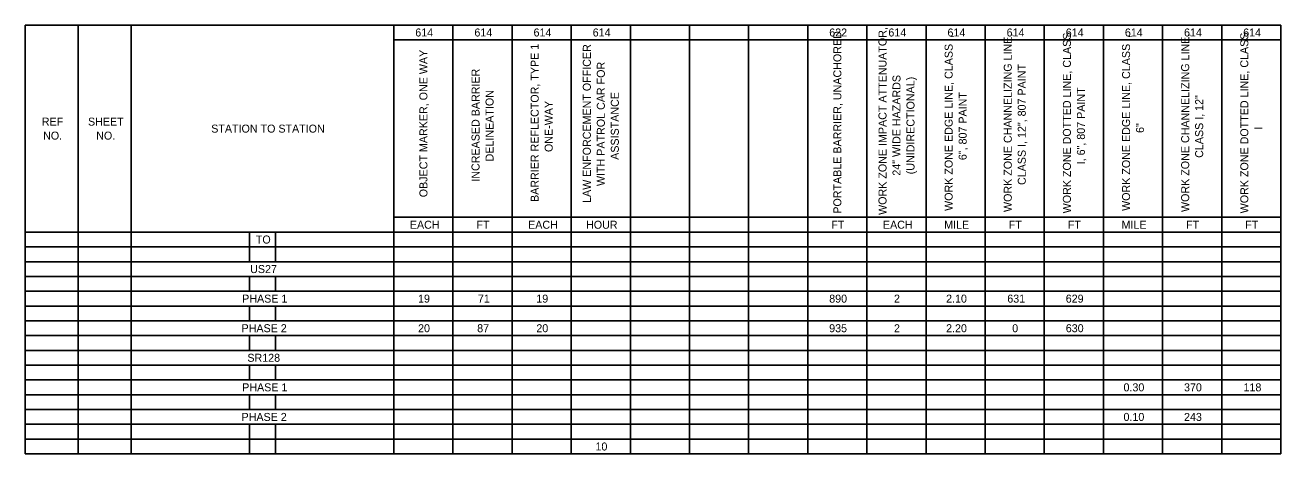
# Model space of a CAD drawing. Extents: x 0 to 86.6, y -18.4 to 22.
# Drawn here: x 52.83 to 86.56, y 9.09 to 20.61 of the extents above; entities that cross this region are included whole.
import ezdxf

# ---------------------------------------------------------------- set-up
doc = ezdxf.new("R2010")
doc.units = 0
doc.layers.add('SH_Text', color=7, linetype='Continuous')

msp = doc.modelspace()

# ---------------------------------------------------------------- linework, layer by layer
at = {"layer": 'SH_Text'}
for p, q in [((52.826, 20.609), (86.562, 20.609)), ((52.826, 20.609), (52.826, 9.091)), ((54.251, 20.609), (54.251, 9.091)), ((55.677, 20.609), (55.677, 9.091)), ((62.732, 20.609), (62.732, 9.091)), ((64.321, 20.609), (64.321, 9.091)), ((65.909, 20.609), (65.909, 9.091)), ((67.498, 20.609), (67.498, 9.091)), ((69.087, 20.609), (69.087, 9.091)), ((70.675, 20.609), (70.675, 9.091)), ((72.264, 20.609), (72.264, 9.091)), ((73.853, 20.609), (73.853, 9.091)), ((75.441, 20.609), (75.441, 9.091)), ((77.03, 20.609), (77.03, 9.091)), ((78.619, 20.609), (78.619, 9.091)), ((80.207, 20.609), (80.207, 9.091)), ((81.796, 20.609), (81.796, 9.091)), ((83.385, 20.609), (83.385, 9.091)), ((84.973, 20.609), (84.973, 9.091)), ((86.562, 20.609), (86.562, 9.091)), ((62.732, 20.212), (86.562, 20.212)), ((62.732, 15.446), (86.562, 15.446)), ((52.826, 15.048), (86.562, 15.048)), ((58.854, 15.048), (58.854, 14.254)), ((59.555, 15.048), (59.555, 14.254)), ((52.826, 14.651), (86.562, 14.651)), ((52.826, 14.254), (86.562, 14.254)), ((52.826, 13.857), (86.562, 13.857)), ((58.854, 13.857), (58.854, 13.46)), ((59.555, 13.857), (59.555, 13.46)), ((52.826, 13.46), (86.562, 13.46)), ((52.826, 13.063), (86.562, 13.063)), ((58.854, 13.063), (58.854, 12.665)), ((59.555, 13.063), (59.555, 12.665)), ((52.826, 12.665), (86.562, 12.665)), ((52.826, 12.268), (86.562, 12.268)), ((58.854, 12.268), (58.854, 11.871)), ((59.555, 12.268), (59.555, 11.871)), ((52.826, 11.871), (86.562, 11.871)), ((52.826, 11.474), (86.562, 11.474)), ((58.854, 11.474), (58.854, 11.077)), ((59.555, 11.474), (59.555, 11.077)), ((52.826, 11.077), (86.562, 11.077)), ((52.826, 10.68), (86.562, 10.68)), ((58.854, 10.68), (58.854, 10.282)), ((59.555, 10.68), (59.555, 10.282)), ((52.826, 10.282), (86.562, 10.282)), ((52.826, 9.885), (86.562, 9.885)), ((58.854, 9.885), (58.854, 9.091)), ((59.555, 9.885), (59.555, 9.091)), ((52.826, 9.488), (86.562, 9.488)), ((52.826, 9.091), (86.562, 9.091))]:
    msp.add_line(p, q, dxfattribs=at)

# ---------------------------------------------------------------- texts
for s, height, p in [('614', 0.2149, (63.308, 20.303)), ('614', 0.2149, (64.896, 20.303)), ('614', 0.2149, (66.485, 20.303)), ('614', 0.2149, (68.074, 20.303)), ('622', 0.2149, (74.429, 20.303)), ('614', 0.2149, (76.017, 20.303)), ('614', 0.2149, (77.605, 20.303)), ('614', 0.2149, (79.194, 20.303)), ('614', 0.2149, (80.783, 20.303)), ('614', 0.2149, (82.371, 20.303)), ('614', 0.2149, (83.96, 20.303)), ('614', 0.2149, (85.549, 20.303)), ('REF', 0.2149, (53.275, 17.909)), ('SHEET', 0.2149, (54.516, 17.909)), ('STATION TO STATION', 0.21494, (57.826, 17.721)), ('NO.', 0.2149, (53.31, 17.533)), ('NO.', 0.2149, (54.736, 17.533)), ('EACH', 0.2149, (63.162, 15.139)), ('FT', 0.2149, (64.953, 15.139)), ('EACH', 0.2149, (66.339, 15.139)), ('HOUR', 0.2149, (67.896, 15.139)), ('FT', 0.2149, (74.485, 15.139)), ('EACH', 0.2149, (75.871, 15.139)), ('MILE', 0.2149, (77.516, 15.139)), ('FT', 0.2149, (79.25, 15.139)), ('FT', 0.2149, (80.839, 15.139)), ('MILE', 0.2149, (82.282, 15.139)), ('FT', 0.2149, (84.016, 15.139)), ('FT', 0.2149, (85.605, 15.139)), ('TO', 0.2149, (59.025, 14.742)), ('US27', 0.2149, (58.872, 13.948)), ('PHASE 1', 0.2149, (58.658, 13.154)), ('19', 0.2149, (63.382, 13.154)), ('71', 0.2149, (64.99, 13.154)), ('19', 0.2149, (66.559, 13.154)), ('890', 0.2149, (74.428, 13.154)), ('2', 0.215, (76.168, 13.154)), ('2.10', 0.2149, (77.568, 13.154)), ('631', 0.2149, (79.212, 13.154)), ('629', 0.2149, (80.782, 13.154)), ('PHASE 2', 0.2149, (58.641, 12.359)), ('20', 0.2149, (63.383, 12.359)), ('87', 0.2149, (64.971, 12.359)), ('20', 0.2149, (66.56, 12.359)), ('935', 0.2149, (74.427, 12.359)), ('2', 0.215, (76.168, 12.359)), ('2.20', 0.2149, (77.568, 12.359)), ('0', 0.215, (79.344, 12.359)), ('630', 0.2149, (80.783, 12.359)), ('SR128', 0.2149, (58.797, 11.565)), ('PHASE 1', 0.2149, (58.658, 10.771)), ('0.30', 0.2149, (82.334, 10.771)), ('370', 0.2149, (83.96, 10.771)), ('118', 0.2149, (85.558, 10.771)), ('PHASE 2', 0.2149, (58.641, 9.976)), ('0.10', 0.2149, (82.334, 9.976)), ('243', 0.2149, (83.96, 9.976)), ('10', 0.2149, (68.149, 9.182))]:
    msp.add_text(s, height=height, dxfattribs=at).set_placement(p)
for s, height, p in [('PORTABLE BARRIER, UNACHORED', 0.21494, (74.754, 15.543)), ('WORK ZONE IMPACT ATTENUATOR, ', 0.21494, (75.967, 15.51)), ('WORK ZONE EDGE LINE, CLASS I, ', 0.21494, (77.744, 15.618)), ('WORK ZONE CHANNELIZING LINE, ', 0.21494, (79.332, 15.588)), ('WORK ZONE DOTTED LINE, CLASS ', 0.21494, (80.921, 15.553)), ('WORK ZONE EDGE LINE, CLASS I, ', 0.21494, (82.51, 15.618)), ('WORK ZONE CHANNELIZING LINE, ', 0.21494, (84.098, 15.588)), ('WORK ZONE DOTTED LINE, CLASS ', 0.21494, (85.687, 15.553)), ('OBJECT MARKER, ONE WAY', 0.21494, (63.634, 15.985)), ('BARRIER REFLECTOR, TYPE 1 ', 0.21494, (66.623, 15.858)), ('LAW ENFORCEMENT OFFICER ', 0.21494, (68.024, 15.833)), ('WITH PATROL CAR FOR ', 0.21494, (68.4, 16.286)), ('INCREASED BARRIER ', 0.21494, (65.034, 16.403)), ('24" WIDE HAZARDS ', 0.21494, (76.343, 16.564)), ('CLASS I, 12", 807 PAINT', 0.21494, (79.708, 16.314)), ('(UNIDIRECTIONAL)', 0.21494, (76.719, 16.602)), ('I, 6", 807 PAINT', 0.21494, (81.297, 16.87)), ('DELINEATION', 0.21494, (65.411, 16.948)), ('ONE-WAY', 0.2149, (66.999, 17.199)), ('ASSISTANCE', 0.2149, (68.776, 16.99)), ('6", 807 PAINT', 0.21494, (78.12, 16.982)), ('CLASS I, 12"', 0.21494, (84.474, 17.043)), ('6"', 0.2149, (82.886, 17.712)), ('I', 0.215, (86.063, 17.803))]:
    msp.add_text(s, height=height, rotation=90, dxfattribs=at).set_placement(p)

doc.saveas('drawing.dxf')
